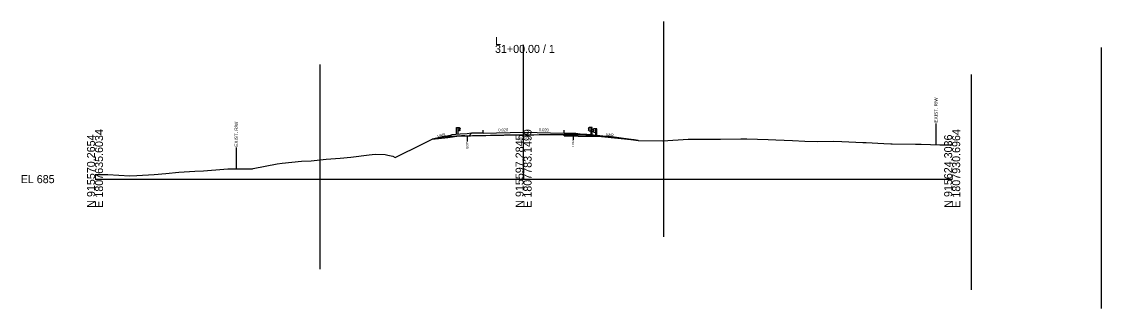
# Model space of a CAD drawing. Extents: x -26 to 1352, y -510 to 9596.
# Drawn here: x 974.3 to 1352.2, y 6954.8 to 7055.1 of the extents above; entities that cross this region are included whole.
import ezdxf

# ---------------------------------------------------------------- set-up
doc = ezdxf.new("R2010")
doc.units = 0
for name, color, linetype in [('Exist Cross Section Cell', 7, 'Continuous'), ('Exist XS Center Line Elevation Label', 7, 'Continuous'), ('Exist XS Ground Line', 7, 'Continuous'), ('Old_Level_10', 7, 'Continuous'), ('Prop XS Ditch Slope Text', 7, 'Continuous'), ('Prop XS Earthwork Shape', 7, 'Continuous'), ('Prop XS EOT Tick Mark', 7, 'Continuous'), ('Prop XS Exc Vertical Line 1', 7, 'Continuous'), ('Prop XS Exc Vertical Line 2', 7, 'Continuous'), ('Prop XS Exc Vertical Line 3', 7, 'Continuous'), ('Prop XS Exc Vertical Line 4', 7, 'Continuous'), ('Prop XS Finish Grade', 7, 'Continuous'), ('Prop XS Finish Grade Earthwork', 7, 'Continuous'), ('Prop XS Finish Grade Paved Shoulder', 7, 'Continuous'), ('Prop XS Finish Grade Pavement', 7, 'Continuous'), ('Prop XS Guardrail', 7, 'Continuous'), ('Prop XS Pvmt Edge Slope', 7, 'Continuous'), ('Prop XS SE Text', 7, 'Continuous'), ('Prop XS Subgrade Earthwork', 7, 'Continuous'), ('Scratch_Level_6', 7, 'Continuous')]:
    doc.layers.add(name, color=color, linetype=linetype)

msp = doc.modelspace()

# ---------------------------------------------------------------- linework, layer by layer
at = {"layer": 'Exist Cross Section Cell'}
for p, q in [((1150, 7000), (1150, 7046.94)), ((1000, 7000), (1150, 7000)), ((1150, 7000), (1300, 7000))]:
    msp.add_line(p, q, dxfattribs=at)
at = {"layer": 'Exist XS Ground Line'}
msp.add_lwpolyline([(1000, 7001.59), (1003.55, 7001.62), (1004.47, 7001.67), (1012.14, 7001.2), (1014.64, 7001.28), (1020.74, 7001.61), (1024.8, 7001.96), (1029.33, 7002.4), (1034.97, 7002.74), (1037.92, 7002.92), (1045.13, 7003.53), (1046.51, 7003.59), (1054.04, 7003.66), (1055.11, 7003.66), (1055.3, 7003.7), (1063.7, 7005.35), (1065.47, 7005.63), (1072.29, 7006.3), (1075.63, 7006.46), (1080.88, 7007.03), (1085.8, 7007.38), (1089.48, 7007.66), (1095.97, 7008.55), (1098.07, 7008.73), (1101.59, 7008.59), (1102.44, 7008.36), (1104.28, 7008.08), (1105.03, 7007.6), (1114.69, 7012.34), (1118.03, 7014.03), (1123.44, 7014.58), (1128.27, 7015.22), (1129.08, 7015.22), (1129.15, 7015.22), (1129.31, 7015.21), (1129.59, 7015.2), (1130.18, 7015.18), (1130.27, 7015.18), (1130.75, 7015.18), (1131.46, 7015.2), (1132.16, 7015.22), (1132.25, 7015.22), (1133.3, 7015.23), (1133.69, 7015.24), (1135.84, 7015.28), (1136.81, 7015.31), (1138.39, 7015.36), (1139.47, 7015.37), (1140.93, 7015.37), (1143.03, 7015.43), (1143.46, 7015.44), (1145.14, 7015.47), (1145.25, 7015.47), (1145.64, 7015.48), (1146, 7015.48), (1146.47, 7015.49), (1147.25, 7015.49), (1147.53, 7015.5), (1148.55, 7015.51), (1149.8, 7015.53), (1149.97, 7015.53), (1150, 7015.53), (1150.24, 7015.53), (1151.09, 7015.53), (1152.37, 7015.53), (1153.63, 7015.52), (1155.48, 7015.56), (1156.17, 7015.57), (1158.59, 7015.56), (1158.72, 7015.56), (1159.28, 7015.58), (1161.47, 7015.62), (1161.75, 7015.62), (1162.34, 7015.62), (1163.8, 7015.63), (1165.25, 7015.63), (1166.34, 7015.63), (1166.95, 7015.64), (1167.3, 7015.64), (1167.41, 7015.65), (1167.76, 7015.63), (1170.63, 7015.6), (1177.26, 7014.97), (1188.72, 7013.7), (1190.13, 7013.54), (1190.23, 7013.54), (1198.68, 7013.41), (1207.59, 7013.96), (1208.26, 7013.96), (1211.9, 7013.99), (1218.93, 7013.98), (1226.08, 7014.06), (1226.96, 7014.06), (1228.13, 7014.05), (1235.55, 7013.82), (1238.29, 7013.75), (1244.15, 7013.47), (1248.46, 7013.28), (1252.74, 7013.18), (1258.63, 7013.23), (1261.33, 7013.2), (1268.79, 7012.83), (1269.93, 7012.79), (1276.11, 7012.45), (1278.52, 7012.33), (1278.96, 7012.32), (1287.11, 7012.19), (1289.13, 7012.2), (1295.7, 7012.05), (1299.29, 7012), (1300, 7011.99)], dxfattribs=at)
at = {"layer": 'Old_Level_10'}
for p, q in [((1294.3, 7019.49), (1294.3, 7012.08)), ((1130.27, 7015.18), (1130.27, 7013.13)), ((1167.3, 7015.64), (1167.3, 7013.59)), ((1049.44, 7011.02), (1049.44, 7003.62))]:
    msp.add_line(p, q, dxfattribs=at)
at = {"layer": 'Prop XS Earthwork Shape'}
for points in [[(1123.44, 7014.58), (1126.54, 7014.99), (1122.17, 7014.91), (1118.03, 7014.03)], [(1123.44, 7014.58), (1126.54, 7014.99), (1122.17, 7014.91), (1118.03, 7014.03)], [(1123.44, 7014.58), (1126.54, 7014.99), (1122.17, 7014.91), (1118.03, 7014.03)], [(1118.03, 7014.03), (1122.17, 7014.91), (1126.54, 7014.99), (1123.44, 7014.58)], [(1135.81, 7015.18), (1130.88, 7015.08), (1126.54, 7014.99), (1128.27, 7015.22), (1129.08, 7015.22), (1129.15, 7015.22), (1129.31, 7015.21), (1129.59, 7015.2), (1130.18, 7015.18), (1130.27, 7015.18), (1130.75, 7015.18), (1131.46, 7015.2), (1132.16, 7015.22), (1132.25, 7015.22), (1133.3, 7015.23), (1133.69, 7015.24), (1135.81, 7015.28)], [(1133.69, 7015.24), (1135.81, 7015.28), (1135.81, 7015.18), (1130.88, 7015.08), (1126.54, 7014.99), (1128.27, 7015.22), (1129.08, 7015.22), (1129.15, 7015.22), (1129.31, 7015.21), (1129.59, 7015.2), (1130.18, 7015.18), (1130.27, 7015.18), (1130.75, 7015.18), (1131.46, 7015.2), (1132.16, 7015.22), (1132.25, 7015.22), (1133.3, 7015.23)], [(1129.08, 7015.22), (1129.15, 7015.22), (1129.31, 7015.21), (1129.59, 7015.2), (1130.18, 7015.18), (1130.27, 7015.18), (1130.75, 7015.18), (1131.46, 7015.2), (1132.16, 7015.22), (1132.25, 7015.22), (1133.3, 7015.23), (1133.69, 7015.24), (1135.81, 7015.28), (1135.81, 7015.18), (1130.88, 7015.08), (1126.54, 7014.99), (1128.27, 7015.22)], [(1129.08, 7015.22), (1129.15, 7015.22), (1129.31, 7015.21), (1129.59, 7015.2), (1130.18, 7015.18), (1130.27, 7015.18), (1130.75, 7015.18), (1131.46, 7015.2), (1132.16, 7015.22), (1132.25, 7015.22), (1133.3, 7015.23), (1133.69, 7015.24), (1135.81, 7015.28), (1135.81, 7015.18), (1130.88, 7015.08), (1126.54, 7014.99), (1128.27, 7015.22)], [(1135.81, 7015.18), (1130.88, 7015.08), (1126.54, 7014.99), (1128.27, 7015.22), (1129.08, 7015.22), (1129.15, 7015.22), (1129.31, 7015.21), (1129.59, 7015.2), (1130.18, 7015.18), (1130.27, 7015.18), (1130.75, 7015.18), (1131.46, 7015.2), (1132.16, 7015.22), (1132.25, 7015.22), (1133.3, 7015.23), (1133.69, 7015.24), (1135.81, 7015.28)], [(1166.95, 7015.64), (1167.3, 7015.64), (1167.41, 7015.65), (1167.76, 7015.63), (1170.63, 7015.6), (1177.26, 7014.97), (1177.86, 7014.9), (1169.12, 7015.08), (1164.19, 7015.18), (1164.19, 7015.63), (1165.25, 7015.63), (1166.34, 7015.63)], [(1169.12, 7015.08), (1177.86, 7014.9), (1177.26, 7014.97), (1170.63, 7015.6), (1167.76, 7015.63), (1167.41, 7015.65), (1167.3, 7015.64), (1166.95, 7015.64), (1166.34, 7015.63), (1165.25, 7015.63), (1164.19, 7015.63), (1164.19, 7015.18)], [(1169.12, 7015.08), (1177.86, 7014.9), (1177.26, 7014.97), (1170.63, 7015.6), (1167.76, 7015.63), (1167.41, 7015.65), (1167.3, 7015.64), (1166.95, 7015.64), (1166.34, 7015.63), (1165.25, 7015.63), (1164.19, 7015.63), (1164.19, 7015.18)], [(1169.12, 7015.08), (1177.86, 7014.9), (1177.26, 7014.97), (1170.63, 7015.6), (1167.76, 7015.63), (1167.41, 7015.65), (1167.3, 7015.64), (1166.95, 7015.64), (1166.34, 7015.63), (1165.25, 7015.63), (1164.19, 7015.63), (1164.19, 7015.18)], [(1188.72, 7013.7), (1190.13, 7013.54), (1179.95, 7014.86), (1177.86, 7014.9)], [(1179.95, 7014.86), (1190.13, 7013.54), (1188.72, 7013.7), (1177.86, 7014.9)], [(1179.95, 7014.86), (1190.13, 7013.54), (1188.72, 7013.7), (1177.86, 7014.9)], [(1179.95, 7014.86), (1190.13, 7013.54), (1188.72, 7013.7), (1177.86, 7014.9)], [(1188.72, 7013.7), (1190.13, 7013.54), (1179.95, 7014.86), (1177.86, 7014.9)]]:
    msp.add_lwpolyline(points, close=True, dxfattribs=at)
at = {"layer": 'Prop XS EOT Tick Mark'}
for p, q in [((1135.81, 7016.1), (1135.81, 7017.1)), ((1164.19, 7016.1), (1164.19, 7017.1))]:
    msp.add_line(p, q, dxfattribs=at)
at = {"layer": 'Prop XS Exc Vertical Line 1'}
msp.add_line((1078.83, 6968.49), (1078.83, 7040.14), dxfattribs=at)
at = {"layer": 'Prop XS Exc Vertical Line 2'}
msp.add_line((1199.04, 6979.85), (1199.04, 7055.09), dxfattribs=at)
at = {"layer": 'Prop XS Exc Vertical Line 3'}
msp.add_line((1306.75, 6961.32), (1306.75, 7036.56), dxfattribs=at)
at = {"layer": 'Prop XS Exc Vertical Line 4'}
msp.add_line((1352.23, 6954.81), (1352.23, 7046), dxfattribs=at)
at = {"layer": 'Prop XS Finish Grade'}
for p, q in [((1122.17, 7014.91), (1124.76, 7015.45)), ((1127.81, 7015.7), (1124.76, 7015.45)), ((1130.24, 7015.89), (1127.81, 7015.7)), ((1131.81, 7016.02), (1130.24, 7015.89)), ((1168.19, 7016.02), (1169.76, 7015.89)), ((1169.76, 7015.89), (1172.19, 7015.7)), ((1172.19, 7015.7), (1175.69, 7015.42)), ((1175.69, 7015.42), (1179.95, 7014.86)), ((1179.95, 7014.86), (1179.95, 7014.86))]:
    msp.add_line(p, q, dxfattribs=at)
at = {"layer": 'Prop XS Finish Grade Earthwork'}
for p, q in [((1118.03, 7014.03), (1122.17, 7014.91)), ((1179.95, 7014.86), (1190.13, 7013.54))]:
    msp.add_line(p, q, dxfattribs=at)
at = {"layer": 'Prop XS Finish Grade Paved Shoulder'}
for p, q in [((1135.81, 7016.1), (1131.81, 7016.02)), ((1164.19, 7016.1), (1168.19, 7016.02))]:
    msp.add_line(p, q, dxfattribs=at)
at = {"layer": 'Prop XS Finish Grade Pavement'}
for p, q in [((1135.81, 7016.1), (1150, 7016.38)), ((1150, 7016.38), (1164.19, 7016.1))]:
    msp.add_line(p, q, dxfattribs=at)
at = {"layer": 'Prop XS Guardrail'}
for p, q in [((1126.47, 7018.06), (1126.97, 7018.06)), ((1126.47, 7015.56), (1126.47, 7018.06)), ((1126.97, 7018.06), (1126.97, 7015.56)), ((1126.97, 7018.06), (1127.47, 7018.06)), ((1127.47, 7018.06), (1127.76, 7017.86)), ((1172.98, 7018.07), (1172.69, 7017.87)), ((1173.48, 7018.07), (1172.98, 7018.07)), ((1173.48, 7018.07), (1173.48, 7015.57)), ((1173.98, 7018.07), (1173.48, 7018.07)), ((1173.98, 7015.57), (1173.98, 7018.07)), ((1127.47, 7016.93), (1126.97, 7016.93)), ((1127.76, 7017.74), (1127.47, 7017.54)), ((1127.47, 7017.54), (1127.47, 7017.45)), ((1127.47, 7017.45), (1127.76, 7017.25)), ((1127.76, 7017.13), (1127.47, 7016.93)), ((1127.76, 7017.86), (1127.79, 7017.8)), ((1127.79, 7017.8), (1127.76, 7017.74)), ((1127.76, 7017.25), (1127.79, 7017.19)), ((1127.79, 7017.19), (1127.76, 7017.13)), ((1172.69, 7017.87), (1172.66, 7017.81)), ((1172.66, 7017.81), (1172.69, 7017.75)), ((1172.69, 7017.26), (1172.66, 7017.2)), ((1172.66, 7017.2), (1172.69, 7017.14)), ((1172.69, 7017.75), (1172.98, 7017.55)), ((1172.98, 7017.46), (1172.69, 7017.26)), ((1172.69, 7017.14), (1172.98, 7016.94)), ((1172.98, 7017.55), (1172.98, 7017.46)), ((1172.98, 7016.94), (1173.48, 7016.94))]:
    msp.add_line(p, q, dxfattribs=at)
at = {"layer": 'Prop XS Pvmt Edge Slope'}
for p, q in [((1131.81, 7016.02), (1130.88, 7015.08)), ((1168.19, 7016.02), (1169.12, 7015.08))]:
    msp.add_line(p, q, dxfattribs=at)
at = {"layer": 'Prop XS Subgrade Earthwork'}
for p, q in [((1130.88, 7015.08), (1122.17, 7014.91)), ((1135.81, 7015.18), (1130.88, 7015.08)), ((1135.81, 7015.28), (1135.81, 7015.18)), ((1164.19, 7015.63), (1164.19, 7015.18)), ((1164.19, 7015.18), (1169.12, 7015.08)), ((1169.12, 7015.08), (1179.95, 7014.86))]:
    msp.add_line(p, q, dxfattribs=at)
at = {"layer": 'Scratch_Level_6'}
for p, q in [((1174.34, 7017.42), (1174.31, 7017.36)), ((1174.31, 7017.36), (1174.34, 7017.3)), ((1174.34, 7016.8), (1174.31, 7016.74)), ((1174.31, 7016.74), (1174.34, 7016.68)), ((1174.63, 7017.62), (1174.34, 7017.42)), ((1174.34, 7017.3), (1174.63, 7017.1)), ((1174.63, 7017), (1174.34, 7016.8)), ((1174.34, 7016.68), (1174.63, 7016.48)), ((1175.13, 7017.62), (1174.63, 7017.62)), ((1174.63, 7017.1), (1174.63, 7017)), ((1174.63, 7016.48), (1175.13, 7016.48)), ((1175.63, 7017.62), (1175.13, 7017.62)), ((1175.13, 7017.62), (1175.13, 7015.12)), ((1175.63, 7015.12), (1175.63, 7017.62))]:
    msp.add_line(p, q, dxfattribs=at)

# ---------------------------------------------------------------- texts
at = {"layer": 'Exist Cross Section Cell'}
for s, p in [('L', (1140, 7046.94)), ('31+00.00 / 1', (1140, 7044.14)), ('EL 685', (974, 6998.6))]:
    msp.add_text(s, height=2.8, dxfattribs=at).set_placement(p)
for s, p in [('N 915570.2654', (1000, 6990)), ('E 1807635.6034', (1002.8, 6990)), ('N 915597.2845', (1150, 6990)), ('E 1807783.1499', (1152.8, 6990)), ('N 915624.3036', (1300, 6990)), ('E 1807930.6964', (1302.8, 6990))]:
    msp.add_text(s, height=2.8, rotation=90, dxfattribs=at).set_placement(p)
at = {"layer": 'Exist XS Center Line Elevation Label'}
msp.add_text('700.53', height=1, dxfattribs=at).set_placement((1147.95, 7013.53))
at = {"layer": 'Old_Level_10'}
for s, height, p in [('EXIST. R/W', 1.181, (1294.89, 7019.79)), ('EXIST. R/W', 1.181, (1050.03, 7011.32)), ('EOP', 0.787, (1130.66, 7010.73)), ('EOP', 0.787, (1167.69, 7011.2))]:
    msp.add_text(s, height=height, rotation=90, dxfattribs=at).set_placement(p)
at = {"layer": 'Prop XS Ditch Slope Text'}
for rotation, p in [(14.0362, (1119.91, 7014.5)), (352.8738, (1178.67, 7015.17))]:
    msp.add_text('VAR.', height=1, rotation=rotation, dxfattribs=at).set_placement(p)
at = {"layer": 'Prop XS SE Text'}
for rotation, p in [(1.1458, (1141.16, 7016.7)), (358.8542, (1155.34, 7016.77))]:
    msp.add_text('0.020', height=1, rotation=rotation, dxfattribs=at).set_placement(p)

doc.saveas('drawing.dxf')
